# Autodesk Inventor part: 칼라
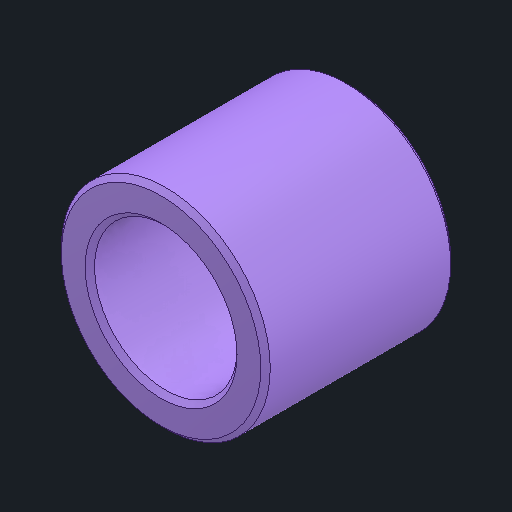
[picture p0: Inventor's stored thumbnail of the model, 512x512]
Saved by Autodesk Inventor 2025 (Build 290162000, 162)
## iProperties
Created: 2025-08
Part Number: 칼라
Material: 스테인리스강
Document SubType Name: Modeling
Designer: infra15
Density: 8.08 g/cm^3
Appearance: 기본값
Author: jhkim
Sending System: Autodesk Inventor 2026
Preprocessor: ST-DEVELOPER v20.1
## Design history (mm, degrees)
feature "솔리드1"
node "솔리드2"
